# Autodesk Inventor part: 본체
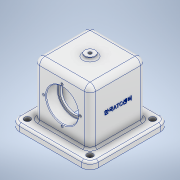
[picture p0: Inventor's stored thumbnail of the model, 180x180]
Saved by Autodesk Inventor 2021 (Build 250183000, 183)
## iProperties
Created: 2022-07
Part Number: 본체
Material: 알루미늄 6061
Document SubType Name: Modeling
Designer: j
Mass: 1059.83 g
Surface Area: 721.846 cm^2
Volume: 392.53 cm^3
Density: 2.7 g/cm^3
Appearance: 알루미늄 - 평지
Author: j
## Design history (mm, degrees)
sketch "스케치1"
  geometry: L1 (58, 58)-(-58, 58); L2 (-58, 58)-(-58, -58); L3 (-58, -58)-(58, -58); L4 (58, -58)-(58, 58); L5 (58, 58)-(-58, -58); L6 (-58, 58)-(58, -58); 1 further point
  constraints: 12 end point, 2 midpoint, 2 parallel, 1 horizontal, 1 perpendicular
  dimensions: "d0" = 116 distance of L3.end L2.end; "d1" = 116 distance of L2.end L1.end
extrude "돌출1" new body sketch "스케치1" distance "d2" = 10; taper "d3" = 0 deg
sketch "스케치2"
  geometry: L1 (-41, -41)-(41, -41); L2 (41, -41)-(41, 41); L3 (41, 41)-(-41, 41); L4 (-41, 41)-(-41, -41); L5 (-41, -41)-(41, 41); L6 (41, -41)-(-41, 41); 1 further point
  constraints: 12 end point, 2 midpoint, 2 parallel, 1 horizontal, 1 perpendicular
  dimensions: "d4" = 82 distance of L3.end L2.end; "d5" = 82 distance of L2.end L1.end
extrude "돌출2" join sketch "스케치2" distance "d6" = 80; taper "d7" = 0 deg
sketch "스케치3"
  geometry: C1 r 7.5 at (0, 0); 1 further point
  constraints: 1 centre point, 1 coincident
  dimensions: "d8" = 15 diameter of C1
extrude "돌출3" join sketch "스케치3" distance "d9" = 4; taper "d10" = 0 deg
sketch "스케치4"
  geometry: L1 (-30, -21)-(30, -21); L2 (30, -21)-(30, 21); L3 (30, 21)-(-30, 21); L4 (-30, 21)-(-30, -21); L5 (-30, -21)-(30, 21); L6 (30, -21)-(-30, 21); C1 r 7.5 at (0, 0) reference; 1 further point
  constraints: 12 end point, 2 midpoint, 2 parallel, 1 horizontal, 1 perpendicular
  dimensions: "d11" = 60 distance of L3.end L2.end; "d12" = 42 distance of L2.end L1.end
extrude "돌출4" cut sketch "스케치4" distance "d13" = 80; taper "d14" = 0 deg
sketch "스케치5"
  geometry: L1 (41, -10)-(41, 38); C1 r 23.5 at (41, 38)
  constraints: 2 end point, 1 centre point, 1 coincident, 1 vertical
  dimensions: "d15" = 48 distance of L1.start L1.end; "d16" = 47 diameter of C1
extrude "돌출5" cut sketch "스케치5" distance "d17" = 17; taper "d18" = 0 deg
sketch "스케치6"
  geometry: C1 r 23.5 at (0, 0) reference; C2 r 20 at (0, 0); 1 further point
  constraints: 1 centre point, 1 coincident
  dimensions: "d19" = 40 diameter of C2
extrude "돌출6" cut sketch "스케치6" extent not by distance; stored distance "d20" = 0; taper "d21" = 0 deg
sketch "스케치7"
  geometry: C1 r 20 at (41, 38) reference; C2 r 23.5 at (41, 38); 1 further point
  constraints: 1 centre point, 1 coincident
  dimensions: "d22" = 47 diameter of C2
extrude "돌출7" cut sketch "스케치7" distance "d23" = 17; taper "d24" = 0 deg
sketch "스케치8"
  geometry: L1 (41, 38)-(41, 65); C1 r 23.5 at (41, 38) reference; 1 further point
  constraints: 2 end point, 1 vertical
  dimensions: "d25" = 27 distance of L1.start L1.end
hole "구멍1" sketch "스케치8" at (41, 65) diameter "d26" = 3.242; stored, may be unused: countersink angle "d30" = 90 deg, drill point angle "d32" = 118 deg; dims "d27" = 8, "d28" = 4, "d29" = 2, "d31" = 10
fillet "모깎기1" dims "d36" = 8
fillet "모깎기2" dims "d37" = 8
fillet "모깎기3" dims "d38" = 3
fillet "모깎기4" dims "d39" = 12
fillet "모깎기5" dims "d40" = 3
fillet "모깎기6" dims "d41" = 3
fillet "모깎기7" dims "d42" = 3
fillet "모깎기8" dims "d43" = 3
sketch "스케치9"
  geometry: C1 r 7.5 at (0, 0) reference; 2 further points
  constraints: 1 coincident
hole "구멍2" sketch "스케치9" at (0, 0) diameter "d44" = 4.917; stored, may be unused: countersink angle "d48" = 90 deg, drill point angle "d50" = 118 deg; dims "d45" = 20, "d46" = 4, "d47" = 2, "d49" = 11.8
fillet "모깎기9" dims "d51" = 0.6
chamfer "모따기1" distance "d52" = 1; stored, may be unused: second distance "d53" = 2, angle "d54" = 45 deg
sketch "스케치10"
  geometry: C1 r 4.5 at (-46, 46); C2 r 4.5 at (46, 46); C3 r 4.5 at (46, -46); C4 r 4.5 at (-46, -46); A1 r 12 centre (-46, 46) between (-46, 58) and (-58, 46) reference; A2 r 9 centre (46, 46) between (55, 46) and (46, 55) reference; A3 r 9 centre (46, -46) between (46, -55) and (55, -46) reference; A4 r 9 centre (-46, -46) between (-55, -46) and (-46, -55) reference; 1 further point
  constraints: 4 centre point, 4 coincident
  dimensions: "d55" = 9 diameter of C1; "d56" = 9 diameter of C2; "d57" = 9 diameter of C3; "d58" = 9 diameter of C4
extrude "돌출8" cut sketch "스케치10" extent not by distance; stored distance "d59" = 0; taper "d60" = 0 deg
sketch "스케치11"
  geometry: L1 (-13, -82)-(79, -82) reference; 3 further points
  constraints: 1 midpoint, 1 vertical alignment, 1 other
  dimensions: "d61" = 48 distance from line of L1 point (33, -34)
feature "엠보싱1" sketch "스케치11" dims "d0" = 116, "d1" = 116, "d62" = 0.5, "d63" = 0
node "솔리드1"
pattern_circular "원형 패턴1" dims angle "d34" = 360 deg
mirror "미러1"
feature "A9D066F2-1C7D-4E18-AEED-F7BC21143FA4" dims "d44" = 4.917, "d45" = 20, "d46" = 4, "d47" = 2, "d48" = 90 deg, "d49" = 11.8, "d50" = 118 deg
